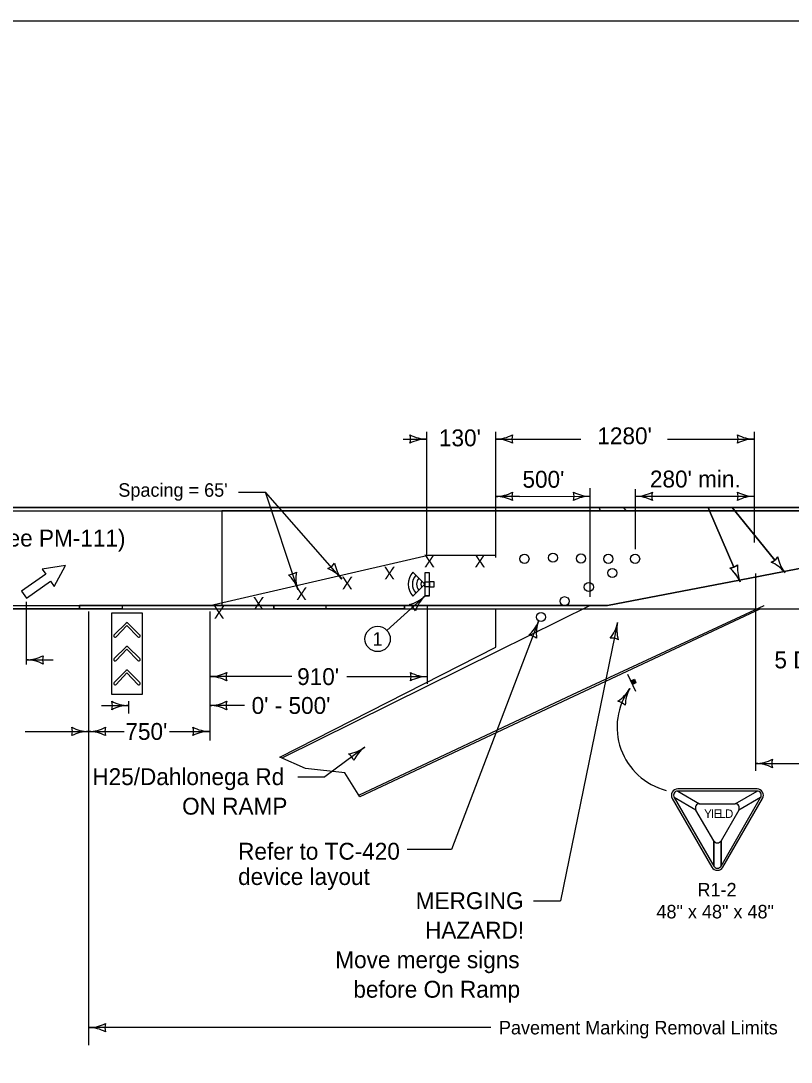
# Model space of a CAD drawing. Extents: x 10133 to 2270741, y 5363 to 1733450.
# Drawn here: x 29111 to 30024, y 8710 to 9944 of the extents above; entities that cross this region are included whole.
import ezdxf

# ---------------------------------------------------------------- set-up
doc = ezdxf.new("R2010")
doc.units = 0
for name, color, linetype in [('dsnNonPlotable', 7, 'Continuous'), ('dsnStdBlockModified', 7, 'Continuous'), ('dsnStdBorder', 7, 'Continuous'), ('Level 12', 7, 'Continuous'), ('Level 2', 7, 'Continuous'), ('SheetBorder', 7, 'Continuous')]:
    doc.layers.add(name, color=color, linetype=linetype)

msp = doc.modelspace()

# ---------------------------------------------------------------- linework, layer by layer
at = {"layer": 'dsnNonPlotable'}
for p, q in [((29334.7, 9251.1), (29593.5, 9310.8)), ((29593.2, 9310.8), (29673.7, 9310.8)), ((29163.7, 9298.2), (29136, 9294.1)), ((29150.3, 9273.7), (29163.7, 9298.2)), ((29140.3, 9288), (29111.6, 9267.9)), ((29136, 9294.1), (29140.3, 9288)), ((29117.4, 9259.7), (29146, 9279.8)), ((29146, 9279.8), (29150.3, 9273.7)), ((29111.6, 9267.9), (29117.4, 9259.7)), ((28166.5, 9251), (29674, 9251)), ((29673.7, 9251), (29785.8, 9251)), ((29785.8, 9251), (29675.5, 9196.4)), ((29992, 9251), (29992.1, 9251)), ((29675.5, 9196.4), (29421, 9070.3))]:
    msp.add_line(p, q, dxfattribs=at)
for points in [[(28167.7, 9363.1), (30246.7, 9363.1)], [(29511.3, 9026.2), (29764.9, 9145.5), (29992, 9251)]]:
    msp.add_lwpolyline(points, dxfattribs=at)
at = {"layer": 'dsnStdBlockModified'}
for p, q in [((29589.7, 9276.2), (29575.5, 9290.3)), ((29595.3, 9289.9), (29589.7, 9289.9)), ((29575.5, 9262), (29589.7, 9276.2)), ((29595.3, 9262.4), (29589.7, 9262.4)), ((29830.1, 9169.5), (29839.6, 9149.3)), ((29836.1, 9157.6), (29834.2, 9161.7)), ((29834.4, 9161.8), (29836.3, 9157.7)), ((29836.5, 9157.8), (29834.6, 9161.9)), ((29834.8, 9162), (29836.7, 9157.9)), ((29836.9, 9157.9), (29834.9, 9162)), ((29835.1, 9162.1), (29837, 9158)), ((29837.3, 9158.1), (29835.3, 9162.2)), ((29835.5, 9162.3), (29837.5, 9158.2)), ((29837.6, 9158.3), (29835.7, 9162.4)), ((29835.9, 9162.5), (29837.9, 9158.4)), ((29838.1, 9158.5), (29836.2, 9162.6)), ((29836.5, 9162.8), (29838.5, 9158.7)), ((29838.6, 9158.8), (29836.7, 9162.9)), ((29837, 9163), (29838.9, 9158.9)), ((29839.1, 9159), (29837.2, 9163.1)), ((29837.4, 9163.2), (29839.3, 9159.1)), ((29839.5, 9159.2), (29837.6, 9163.3)), ((29837.8, 9163.4), (29839.7, 9159.3))]:
    msp.add_line(p, q, dxfattribs=at)
msp.add_lwpolyline([(29835.9, 9157.5), (29833.9, 9161.6), (29838.1, 9163.5), (29840, 9159.4)], close=True, dxfattribs=at)
for radius, start, end in [(20.3, 135.9687, 224.12), (15.3, 136.2841, 223.8335), (10.3, 136.9037, 223.2706), (5.32, 138.7005, 221.2995)]:
    msp.add_arc((29590.2, 9276.2), radius, start, end, dxfattribs=at)
at = {"layer": 'dsnStdBorder'}
for p, q in [((29589.6, 9289.7), (29589.6, 9262.2)), ((29595.3, 9262.4), (29595.3, 9289.9)), ((29237.7, 9230.1), (29251.8, 9216)), ((29237.7, 9202.1), (29251.8, 9188)), ((29237.7, 9173.8), (29251.8, 9159.7)), ((29983.5, 9033.5), (29889.5, 9033.5)), ((29883, 9022.3), (29930, 8940.9)), ((29943, 8940.9), (29990, 9022.3)), ((29932.1, 8972.1), (29932.1, 8942.1)), ((29940.8, 8942.1), (29940.8, 8972.1))]:
    msp.add_line(p, q, dxfattribs=at)
for points in [[(29589.7, 9289.9), (29589.7, 9262.4), (29595.3, 9262.4), (29595.3, 9289.9)], [(29589.7, 9273.2), (29589.7, 9278.9), (29595.3, 9278.9), (29595.3, 9273.2)], [(29595.3, 9278.9), (29595.3, 9273.2), (29600.9, 9273.2), (29600.9, 9278.9)], [(29254.9, 9145.7), (29254.9, 9241.7), (29218.2, 9241.7), (29218.2, 9145.7)], [(29885.1, 9023.5), (29932.1, 8942.1), (29932.1, 8972.1), (29911.1, 9008.5), (29885.1, 9023.5)], [(29983.5, 9031), (29889.5, 9031), (29915.4, 9016), (29957.5, 9016), (29983.5, 9031)], [(29940.8, 8942.1), (29987.8, 9023.5), (29961.8, 9008.5), (29940.8, 8972.1), (29940.8, 8942.1)]]:
    msp.add_lwpolyline(points, close=True, dxfattribs=at)
for points in [[(29221.2, 9216), (29221.3, 9216.1), (29235.4, 9230.2), (29235.4, 9230.2)], [(29249.5, 9213.7), (29249.4, 9213.8), (29236.5, 9227.3), (29223.6, 9213.8)], [(29221.2, 9188), (29221.3, 9188), (29235.4, 9202.1), (29235.4, 9202.1)], [(29249.5, 9185.6), (29249.4, 9185.7), (29236.5, 9199.3), (29223.6, 9185.7)], [(29221.2, 9159.7), (29221.3, 9159.8), (29235.4, 9173.9), (29235.4, 9173.9)], [(29249.5, 9157.4), (29249.4, 9157.5), (29236.5, 9171), (29223.6, 9157.5)]]:
    msp.add_lwpolyline(points, dxfattribs=at)
for centre in [(29707.8, 9306.3), (29707.8, 9306.3), (29741.5, 9307.6), (29741.5, 9307.6), (29774.7, 9306.7), (29774.7, 9306.7), (29807.3, 9306.3), (29807.3, 9306.3), (29839, 9306.3), (29839, 9306.3), (29812, 9289.6), (29812, 9289.6), (29784.1, 9272.8), (29784.1, 9272.8), (29755.3, 9256.1), (29755.3, 9256.1), (29727.4, 9237.3), (29727.4, 9237.3)]:
    msp.add_circle(centre, 5.37, dxfattribs=at)
for centre, radius, start, end in [((29236.5, 9229), 1.65, 44.1616, 134.6098), ((29222.4, 9214.9), 1.65, 136.201, 317.3602), ((29250.6, 9214.9), 1.65, 225.0975, 45.281), ((29236.5, 9200.9), 1.65, 44.1616, 134.6098), ((29222.4, 9186.8), 1.65, 136.201, 317.3602), ((29250.6, 9186.8), 1.65, 225.0975, 45.281), ((29236.5, 9172.7), 1.65, 44.1616, 134.6098), ((29222.4, 9158.6), 1.65, 136.201, 317.3602), ((29250.6, 9158.6), 1.65, 225.0975, 45.281), ((29889.5, 9026), 7.5, 90.0002, 209.9999), ((29889.5, 9026), 5, 89.9999, 210.0002), ((29889.5, 9026), 5, 89.9999, 210.0002), ((29983.5, 9026), 7.5, 330.0002, 89.9999), ((29983.5, 9026), 5, 330.0002, 89.9999), ((29983.5, 9026), 5, 330.0002, 89.9999), ((29915.4, 9011), 5, 90.0002, 209.9999), ((29915.4, 9011), 5, 90.0002, 209.9999), ((29957.5, 9011), 5, 330.0002, 89.9999), ((29957.5, 9011), 5, 330.0002, 89.9999), ((29936.5, 8974.6), 5, 209.9999, 330.0002), ((29936.5, 8944.6), 7.5, 209.9999, 330.0002), ((29936.5, 8944.6), 5, 210.0002, 330.0016)]:
    msp.add_arc(centre, radius, start, end, dxfattribs=at)
at = {"layer": 'Level 12'}
for p, q in [((29592, 9307.8), (29592, 9456.9)), ((29673.7, 9307.8), (29673.7, 9456.9)), ((29980.3, 9325.8), (29980.3, 9456.9)), ((29564, 9448.3), (29592, 9448.3)), ((29673.7, 9448.3), (29774.7, 9448.3)), ((29877.3, 9448.3), (29980.3, 9448.3)), ((29368.6, 9385.4), (29400.6, 9385.4)), ((29491.3, 9282.3), (29400.6, 9385.4)), ((29439, 9270), (29400.6, 9385.4)), ((29785.8, 9261.2), (29785.8, 9390)), ((29839.4, 9317.6), (29839.4, 9388.9)), ((29701.7, 9380.3), (29673.7, 9380.3)), ((29701.7, 9380.3), (29785.8, 9380.4)), ((29839.4, 9380.4), (29958.2, 9380.4)), ((29958.2, 9380.4), (29980.3, 9380.4)), ((29981.7, 9289), (29981.7, 9055.2)), ((29589.6, 9262.2), (29544.8, 9221.4)), ((29117.1, 9255.5), (29117.1, 9180.9)), ((29592.5, 9251.6), (29592.5, 9158.1)), ((29191.1, 9243.7), (29191.1, 8729.9)), ((29334.7, 9243.7), (29334.7, 9090.8)), ((29724.6, 9232.6), (29621.3, 8961.8)), ((29818.2, 9230.9), (29750.6, 8900.9)), ((29117.1, 9186.5), (29149.1, 9186.5)), ((29432, 9166.7), (29334.7, 9166.7)), ((29592.5, 9166.6), (29497.2, 9166.6)), ((29238.4, 9137.7), (29238.4, 9122.8)), ((29206.4, 9132.4), (29238.4, 9132.4)), ((29375.7, 9132.5), (29334.7, 9132.5)), ((29115.8, 9101.7), (29191.1, 9101.7)), ((29191.1, 9101.7), (29233.1, 9101.7)), ((29287, 9101.7), (29334.7, 9101.7)), ((29518.4, 9083.2), (29471.1, 9047.9)), ((29981.7, 9063.7), (30049.3, 9063.7)), ((29439.1, 9047.9), (29471.1, 9047.9)), ((29621.3, 8961.8), (29568.7, 8961.8)), ((29718.6, 8900.9), (29750.6, 8900.9)), ((29668.1, 8750.6), (29191.2, 8750.6))]:
    msp.add_line(p, q, dxfattribs=at)
msp.add_circle((29533.7, 9211.3), 15, dxfattribs=at)
for centre, radius, start, end in [((29556.3, 9448.3), 16.4, 342.2666, 17.7334), ((29592, 9490.8), 42.5, 241.9275, 270), ((29592, 9405.8), 42.5, 90, 118.0725), ((29673.7, 9490.8), 42.5, 270, 298.0725), ((29673.7, 9405.8), 42.5, 61.9275, 90), ((29709.3, 9448.3), 16.4, 162.2666, 197.7334), ((29944.6, 9448.3), 16.4, 342.2666, 17.7334), ((29980.3, 9490.8), 42.5, 241.9275, 270), ((29980.3, 9405.8), 42.5, 90, 118.0725), ((29673.7, 9422.8), 42.5, 270, 298.0725), ((29709.3, 9380.3), 16.4, 162.2666, 197.7334), ((29750.2, 9380.4), 16.4, 342.2666, 17.7333), ((29785.8, 9422.9), 42.5, 241.9275, 270), ((29839.4, 9422.9), 42.5, 270, 298.0725), ((29875, 9380.4), 16.4, 162.2666, 197.7334), ((29944.6, 9380.4), 16.4, 342.2666, 17.7334), ((29980.3, 9422.9), 42.5, 241.9275, 270), ((29673.7, 9337.8), 42.5, 61.9275, 90), ((29785.8, 9337.9), 42.5, 90, 118.0725), ((29839.4, 9337.9), 42.5, 61.9275, 90), ((29980.3, 9337.9), 42.5, 90, 118.0725), ((29469, 9310.2), 16.4, 290.8549, 326.3216), ((29458, 9255.8), 42.5, 38.5882, 66.6607), ((29524.5, 9308.9), 42.5, 190.5158, 218.5882), ((29427.7, 9303.9), 16.4, 270.6739, 306.1406), ((29398.7, 9256.6), 42.5, 18.4072, 46.4797), ((29479.3, 9283.5), 42.5, 170.3348, 198.4072), ((29560.4, 9293), 42.5, 285.3742, 313.4467), ((29618.8, 9231.3), 42.5, 133.4467, 161.5192), ((29563.7, 9237.7), 16.4, 25.7133, 61.18), ((29684.9, 9247.7), 42.5, 311.0454, 339.1178), ((29764.3, 9217.4), 42.5, 159.1178, 187.1903), ((29776.6, 9239.4), 42.5, 320.3573, 348.4298), ((29859.8, 9222.4), 42.5, 168.4298, 196.5023), ((29711.9, 9199.3), 16.4, 51.3845, 86.8512), ((29811.1, 9196), 16.4, 60.6964, 96.1631), ((29117.1, 9229), 42.5, 270, 298.0725), ((29117.1, 9144), 42.5, 61.9275, 90), ((29152.8, 9186.5), 16.4, 162.2666, 197.7334), ((29334.7, 9209.2), 42.5, 270, 298.0725), ((29370.4, 9166.7), 16.4, 162.2666, 197.7334), ((29556.9, 9166.6), 16.4, 342.2666, 17.7334), ((29592.5, 9209.1), 42.5, 241.9275, 270), ((29334.7, 9124.2), 42.5, 61.9275, 90), ((29592.5, 9124.1), 42.5, 90, 118.0725), ((29895.2, 9106.9), 77.6, 143.885, 255.37), ((29795.3, 9173.1), 42.5, 303.1418, 331.2143), ((29869.8, 9132.2), 42.5, 151.2143, 179.2868), ((29202.8, 9132.4), 16.4, 342.2666, 17.7334), ((29238.4, 9174.9), 42.5, 241.9275, 270), ((29334.7, 9175), 42.5, 270, 298.0725), ((29370.4, 9132.5), 16.4, 162.2666, 197.7334), ((29815.3, 9121.4), 16.4, 43.4809, 78.9476), ((29238.4, 9089.9), 42.5, 90, 118.0725), ((29334.7, 9090), 42.5, 61.9275, 90), ((29155.5, 9101.7), 16.4, 342.2666, 17.7334), ((29191.1, 9144.2), 42.5, 241.9275, 270), ((29191.1, 9059.2), 42.5, 90, 118.0725), ((29191.1, 9144.2), 42.5, 270, 298.0725), ((29191.1, 9059.2), 42.5, 61.9275, 90), ((29226.7, 9101.7), 16.4, 162.2666, 197.7334), ((29299.1, 9101.8), 16.4, 342.2666, 17.7334), ((29334.7, 9144.3), 42.5, 241.9275, 270), ((29334.7, 9059.3), 42.5, 90, 118.0725), ((29492.9, 9117.2), 42.5, 278.7086, 306.7811), ((29489.8, 9061.8), 16.4, 19.0477, 54.5145), ((29543.8, 9049.1), 42.5, 126.7811, 154.8536), ((29981.7, 9106.2), 42.5, 270, 298.0725), ((29981.7, 9021.2), 42.5, 61.9275, 90), ((30017.3, 9063.7), 16.4, 162.2666, 197.7334), ((29191.2, 8793.1), 42.5, 270, 298.0725), ((29226.8, 8750.6), 16.4, 162.2666, 197.7334), ((29191.2, 8708.1), 42.5, 61.9275, 90)]:
    msp.add_arc(centre, radius, start, end, dxfattribs=at)
at = {"layer": 'Level 2'}
for p, q in [((28167.7, 9363.1), (29349, 9363.1)), ((28167.7, 9363.1), (29927.3, 9363.1)), ((28171.7, 9367.1), (30262.4, 9367.1)), ((29925.6, 9367.1), (28171.7, 9367.1)), ((29349, 9363.1), (29349, 9251.1)), ((29927.3, 9363.1), (29349, 9363.1)), ((29349, 9363.1), (29349, 9251.1)), ((29796.4, 9367.1), (29825, 9367.1)), ((29798.1, 9363.1), (29796.4, 9367.1)), ((29828.1, 9363.1), (29798.1, 9363.1)), ((29825, 9367.1), (29828.1, 9363.1)), ((29954.1, 9367.1), (29925.6, 9367.1)), ((29925.6, 9367.1), (29927.3, 9363.1)), ((29927.3, 9363.1), (29925.6, 9367.1)), ((29927.3, 9363.1), (29957.3, 9363.1)), ((29955.9, 9296.6), (29927.3, 9363.1)), ((29957.3, 9363.1), (29927.3, 9363.1)), ((29927.3, 9363.1), (29955.9, 9296.6)), ((30249.8, 9367.1), (29954.1, 9367.1)), ((29954.1, 9367.1), (29957.3, 9363.1)), ((29957.3, 9363.1), (29954.1, 9367.1)), ((29957.3, 9363.1), (30251.4, 9363.1)), ((30251.4, 9363.1), (29957.3, 9363.1)), ((29957.3, 9363.1), (30004.6, 9304.7)), ((30004.6, 9304.7), (29957.3, 9363.1)), ((30117.1, 9310.8), (30015.5, 9291.3)), ((30015.5, 9291.3), (30117.1, 9310.8)), ((30015.5, 9291.3), (29962.7, 9281.1)), ((29962.7, 9281.1), (30015.5, 9291.3)), ((30016.7, 9289.8), (30016.3, 9290.3)), ((29806.4, 9251.1), (29962.6, 9281.1)), ((29962.6, 9281.1), (29806.4, 9251.1)), ((28171.7, 9247.1), (30467.9, 9247.1)), ((29180.2, 9247.1), (28171.7, 9247.1)), ((29180.2, 9251.1), (29180.2, 9247.1)), ((29180.2, 9247.1), (29180.2, 9251.1)), ((29180.2, 9251.1), (29231, 9251.1)), ((29231, 9247.1), (29180.2, 9247.1)), ((29472.5, 9251.1), (29231, 9251.1)), ((29231, 9251.1), (29231, 9247.1)), ((29231, 9251.1), (29231, 9247.1)), ((29231, 9247.1), (29472.5, 9247.1)), ((29349, 9251.1), (29410.8, 9251.1)), ((29410.8, 9251.1), (29565.5, 9251.1)), ((29565.5, 9251.1), (29410.8, 9251.1)), ((29410.8, 9251.1), (29410.8, 9247.1)), ((29410.8, 9247.1), (29410.8, 9251.1)), ((29410.8, 9251.1), (29565.5, 9251.1)), ((29565.5, 9247.1), (29410.8, 9247.1)), ((29410.8, 9247.1), (29565.5, 9247.1)), ((29472.5, 9247.1), (29472.5, 9251.1)), ((29565.5, 9247.1), (29565.5, 9251.1)), ((29565.5, 9251.1), (29565.5, 9247.1)), ((29565.5, 9251.1), (29806.4, 9251.1)), ((29806.4, 9251.1), (29565.5, 9251.1)), ((29565.5, 9251.1), (29565.5, 9247.1)), ((29565.5, 9247.1), (30396.1, 9247.1)), ((29673.7, 9201.6), (29673.7, 9247.1)), ((29673.7, 9247.1), (29987.6, 9247.1)), ((29987.6, 9247.1), (29766, 9143.2)), ((29417.9, 9071.4), (29673.7, 9201.6)), ((29766, 9143.2), (29512.6, 9024.1)), ((29448, 9057.9), (29417.9, 9071.4)), ((29494.9, 9052.8), (29448, 9057.9)), ((29512.6, 9024.1), (29494.9, 9052.8))]:
    msp.add_line(p, q, dxfattribs=at)
for points in [[(30015.5, 9291.2), (30015.6, 9291.3)], [(29963.5, 9278.9), (29963.5, 9278.9), (29963.2, 9279.8)], [(29963.2, 9279.7), (29963.2, 9279.8)], [(29349, 9251.1), (29231, 9251.1), (29180.2, 9251.1)]]:
    msp.add_lwpolyline(points, dxfattribs=at)
for centre, radius, start, end in [((29994.5, 9317.6), 16.4, 290.8549, 326.3216), ((29994.5, 9317.6), 16.4, 308.0905, 326.3216), ((30049.9, 9316.3), 42.5, 190.5158, 216.0585), ((30049.9, 9316.3), 42.5, 190.5158, 216.0585), ((29949.8, 9311.8), 16.4, 274.9287, 310.3954), ((29949.8, 9311.8), 16.4, 274.9287, 291.9208), ((29924.3, 9262.5), 42.5, 25.9041, 50.7345), ((29924.3, 9262.5), 42.5, 23.928, 50.7345), ((29949.8, 9311.8), 16.4, 291.9208, 310.3954), ((30002.8, 9295.3), 42.5, 174.5895, 199.4578), ((30002.8, 9295.3), 42.5, 174.5895, 199.4578), ((29994.5, 9317.6), 16.4, 290.8549, 308.0905), ((29983.5, 9263.3), 42.5, 41.1781, 66.6607), ((29983.5, 9263.3), 42.5, 41.1781, 66.6607), ((30049.9, 9316.3), 42.5, 216.0585, 218.5706), ((29983.5, 9263.3), 42.5, 39.4385, 41.1781), ((29983.5, 9263.3), 42.5, 38.5882, 38.6058), ((30049.9, 9316.3), 42.5, 218.5875, 218.5882), ((29924.3, 9262.5), 42.5, 23.928, 25.9041), ((30002.8, 9295.3), 42.5, 199.4578, 202.6444), ((30002.8, 9295.3), 42.5, 199.4578, 201.3966), ((29924.3, 9262.5), 42.5, 22.662, 22.6796)]:
    msp.add_arc(centre, radius, start, end, dxfattribs=at)
at = {"layer": 'SheetBorder'}
msp.add_lwpolyline([(28132.5, 9944), (31267.5, 9944), (31267.5, 7924), (28132.5, 7924)], close=True, dxfattribs=at)

# ---------------------------------------------------------------- texts
at = {"layer": 'dsnStdBorder'}
for s, height, p in [('(See PM-111)', 20, (29068.3, 9320.9)), ('Y', 10, (29920.9, 8999.2)), ('I', 10, (29928.8, 8999.2)), ('E', 10, (29932.3, 8999.2)), ('L', 10, (29939, 8999.2)), ('D', 10, (29945.7, 8999.2)), ('Refer to TC-420', 20, (29368.3, 8949.7)), ('device layout', 20, (29368.3, 8919.7)), ('R1-2', 16, (29912.9, 8906.1)), ('48" x 48" x 48"', 16, (29864.2, 8880.1))]:
    msp.add_text(s, height=height, dxfattribs=at).set_placement(p)
for p in [(29601.9, 9311.4), (29661.7, 9311.4), (29554.5, 9296.9), (29504.4, 9285.2), (29450.1, 9272.5), (29399.3, 9261.1), (29352.5, 9250.4)]:
    msp.add_text('X', height=15, rotation=180, dxfattribs=at).set_placement(p)
at = {"layer": 'Level 12'}
for s, height, p in [("130'", 20, (29606.4, 9439.7)), ("1280'", 20, (29794.2, 9442.1)), ("500'", 20, (29705.4, 9390.6)), ("280' min.", 20, (29856.5, 9390.9)), ("Spacing = 65'", 16, (29226.3, 9379.9)), ('1', 16, (29527.6, 9203.3)), ('5 Devices', 20, (30004.1, 9176.5)), ("910'", 20, (29438.3, 9156.7)), ("0' - 500'", 20, (29384.3, 9122.5)), ("750'", 20, (29234.7, 9091.7)), ('H25/Dahlonega Rd', 20, (29195.5, 9038.1)), ('ON RAMP', 20, (29301.9, 9003.1)), ('MERGING', 20, (29578.9, 8891.1)), (' HAZARD!', 20, (29582.5, 8856.1)), ('Move merge signs', 20, (29483.5, 8821.1)), (' before On Ramp', 20, (29497.5, 8786.1))]:
    msp.add_text(s, height=height, dxfattribs=at).set_placement(p)
msp.add_text('Pavement Marking Removal Limits', height=16, rotation=360, dxfattribs=at).set_placement((29677.5, 8742.6))

doc.saveas('drawing.dxf')
